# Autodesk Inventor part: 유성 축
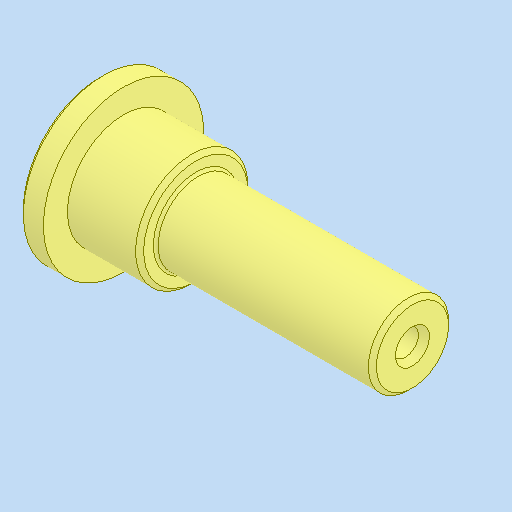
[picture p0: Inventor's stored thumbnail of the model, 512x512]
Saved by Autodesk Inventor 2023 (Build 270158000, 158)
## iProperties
Created: 2026-04
Part Number: 유성 축
Material: 강철, 탄소
Document SubType Name: Modeling
Designer: home
Density: 7.85 g/cm^3
Appearance: 기본값
Author: jhkim
Sending System: Autodesk Inventor 2027
Preprocessor: ST-DEVELOPER v20.1
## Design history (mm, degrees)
feature "솔리드1"
node "솔리드2"
